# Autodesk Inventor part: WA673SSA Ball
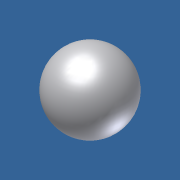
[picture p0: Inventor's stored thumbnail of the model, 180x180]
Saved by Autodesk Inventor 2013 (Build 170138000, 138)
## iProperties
Category: PARTsolutions
Created: 2011-07
Part Number: WA673SSA Ball
Catalog Web Link: www.cadenas.de
Description: Six types ball - Metric system sizes
Document SubType Name: Modeling
Designer: PARTsolutions
Density: 1 g/cm^3
Material: Générique
NB: WA673SSA Ball
NN: Six types ball
NT: Metric system sizes
NBSYN: $ORDER. Ball
LINA: WA673SSA Ball
SD: 3.0
D: 6
B: 2.0
R: 0.08
ORDER: WA673SSA
CR: 242
COR: 94
CRF: 25
CORF: 9,5
LSG: 60 000
LSO: 71 000
MASS: 0.20
ORDER1: 673
D1: 7.2
D2: 7.2
C1: 0.6
C2: 0.6
WSS: WA673SSA
WDS: SSA
UTWF: FL673
FORSS: FLWA673SA
FORDS: SSA
DA1: 3,6
DA2: 4,1
DA: 5,4
RAS: 0,08
MASS1: 0.26
B1: 2.5
VERS: 3
X: 1.500
N: 9
O: 14.130
RB: 0.444
KT: DUMMY
SUPPLIER: NTN
ARTICLENO: WA673SSA Ball
BOMINFO: WA673SSA Ball
CREATOR: CADENAS GmbH
PSOL_IDENT_0: {\\10.0.0.251\ps_data\23d-libs\ntn\ball_roller_bearings\miniature_extra_small_bb\metric_system_sizes
PSOL_IDENT_1: \mss_ball.prj},179 {VTYP=3D},{NB=WA673SSA Ball},{LINA=WA673SSA Ball},{NN=Six types ball},{DATE=11.12
PSOL_IDENT_2: .2007 08:48:23},{GEOMDATE=02.04.2007 00:00:00},{VERSION=},{LINEID=12590},{LINESUBID=-1},{WBVAR=}  {N
PSOL_IDENT_3: B=WA673SSA Ball},{LINA=WA673SSA Ball},{KT=DUMMY},{IDNR=},{SD=3.0},{D=6},{B=2.0},{R=0.08},{ORDER=WA67
PSOL_IDENT_4: 3SSA},{CR=242},{COR=94},{CRF=25},{CORF=9,5},{LSG=60 000},{LSO=71 000},{MASS=0.20},{ORDER1=673},{D1=7
PSOL_IDENT_5: .2},{D2=7.2},{C1=0.6},{C2=0.6},{WSS=WA673SSA},{WDS=SSA},{UTWF=FL673},{FORSS=FLWA673SA},{FORDS=SSA},{
PSOL_IDENT_6: DA1=3,6},{DA2=4,1},{DA=5,4},{RAS=0,08},{MASS1=0.26},{B1=2.5},{VERS=3},{X=1.5},{N=9},{O=14.13},{RB=0.
PSOL_IDENT_7: 444}
Title: WA673SSA Ball
Author: Cadenas PARTsolutions
Comments: Metric system sizes
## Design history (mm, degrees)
sketch "Sketch_1"
  geometry: L1 (0.444, 0)-(-0.444, 0); L2 (0.444, 0)-(-0.444, 0); A1 r 0.444 centre (0, 0) between (0.444, 0) and (-0.444, 0)
  constraints: 4 end point, 2 point on circle, 1 centre point
revolve "Revolution1" sketch "Sketch_1" stored, may be unused: angle "d0" = 360 deg
node "mss_ball_XY"
node "mss_ball_YZ"
node "mss_ball_ZX"
node "mss_ball_X"
node "mss_ball_Y"
node "mss_ball_Z"
node "mss_ball_Center"
node "Solide1"
node "Corps solides"
node "Corps surfaciques"
